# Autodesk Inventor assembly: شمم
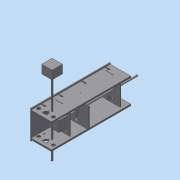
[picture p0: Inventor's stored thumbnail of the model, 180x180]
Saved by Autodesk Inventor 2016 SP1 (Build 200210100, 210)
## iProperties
Created: 2016-06
Part Number: شمم
Document SubType Name: Assembly
Designer: Mohamed A.
Author: Mohamed A.
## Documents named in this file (3)
- C:\Users\Mohamed\Documents\inventor\machine_design\all.iam
- C:\Users\Mohamed\Documents\inventor\machine_design\y-stage\y-stage.iam
- C:\Users\Mohamed\Documents\inventor\machine_design\x-stage\x-stage.iam
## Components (2 placed, 2 different names)
1. y-stage:1 [sub-assembly]
2. x-stage:1 [sub-assembly]
